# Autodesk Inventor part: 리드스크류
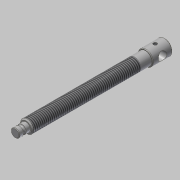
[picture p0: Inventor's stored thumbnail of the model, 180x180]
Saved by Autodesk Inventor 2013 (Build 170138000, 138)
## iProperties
Created: 2019-04
Part Number: 리드스크류
Material: 강철, 연강
Document SubType Name: Modeling
Designer: mduedu
Density: 1 g/cm^3
Author: mduedu
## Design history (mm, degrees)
sketch "스케치1"
  geometry: C1 r 6 at (0, 0); 1 further point
  constraints: 1 centre point, 1 coincident
  dimensions: "d0" = 12 diameter of C1
extrude "돌출1" new body sketch "스케치1" distance "d1" = 110; taper "d2" = 0 deg
sketch "스케치2"
  geometry: C1 r 4 at (0, 0); 1 further point
  constraints: 1 centre point, 1 coincident
  dimensions: "d3" = 8 diameter of C1
extrude "돌출2" join sketch "스케치2" distance "d4" = 10; taper "d5" = 0 deg
sketch "스케치3"
  geometry: C1 r 7 at (0, 0); 1 further point
  constraints: 1 centre point, 1 coincident
  dimensions: "d9" = 14 diameter of C1
extrude "돌출3" join sketch "스케치3" distance "d10" = 18; taper "d11" = 0 deg
feature "스레드1" dims "d12" = 100, "d13" = 0
chamfer "모따기2" distance "d14" = 1; stored, may be unused: second distance "d15" = 2, angle "d16" = 45 deg
chamfer "모따기3" distance "d17" = 0.5; stored, may be unused: second distance "d18" = 2, angle "d19" = 45 deg
chamfer "모따기4" distance "d20" = 0.5; stored, may be unused: second distance "d21" = 2, angle "d22" = 45 deg
sketch "스케치4"
  geometry: L1 (-110, -5)-(-110, 5) reference; L2 (-119.5, 4)-(-119.5, -4) reference; L3 (-119.5, 0)-(-110, 0); C1 r 1.25 at (-115, 4); 1 further point
  constraints: 2 end point, 2 midpoint, 1 centre point
  dimensions: "d23" = 2.5 diameter of C1; "d24" = 5 distance from line of C1.centre L1; "d25" = 4 distance from line of C1.centre L3
revolve "회전1" sketch "스케치4" stored, may be unused: angle "d26" = 90 deg
sketch "스케치5"
  geometry: L1 (0, -6.5)-(0, 6.5) reference; C1 r 4 at (9, 0); 2 further points
  constraints: 1 centre point, 1 horizontal alignment, 1 midpoint
  dimensions: "d27" = 8 diameter of C1; "d28" = 9 distance from line of C1.centre L1
extrude "돌출4" cut sketch "스케치5" stored distance "d29" = 15; taper "d30" = 0 deg
node "작업 평면1"
sketch "스케치6"
  geometry: L1 (0, 6.5)-(0, -6.5) reference; 2 further points
  constraints: 1 horizontal alignment
  dimensions: "d31" = 9 distance from line of point (-9, 0) L1
hole "구멍1" sketch "스케치6" at (-9, 0) diameter "d32" = 3.242; stored, may be unused: countersink angle "d36" = 90 deg, drill point angle "d38" = 118 deg; dims "d33" = 6, "d34" = 4, "d35" = 2, "d37" = 8
node "솔리드1"
